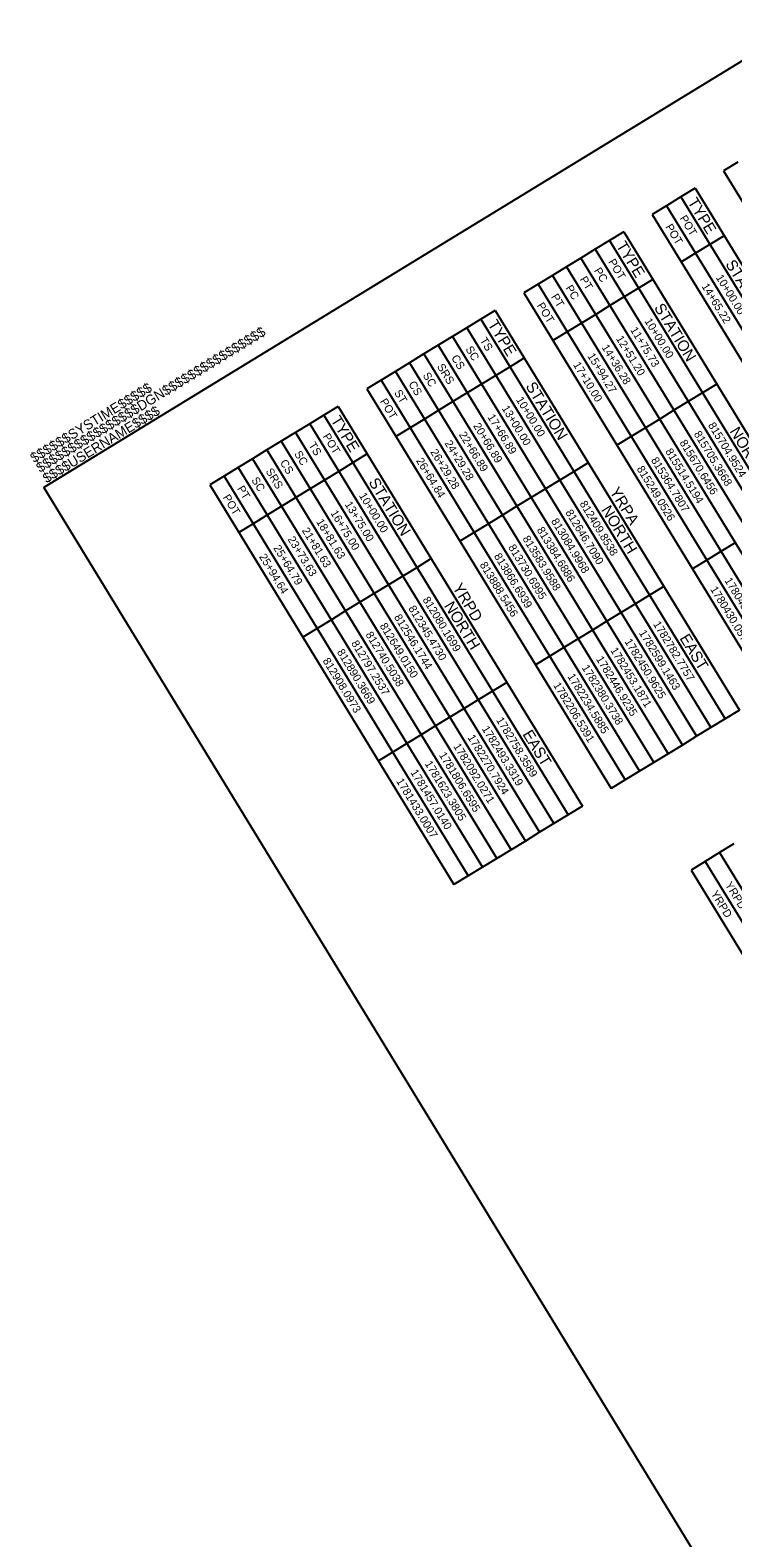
# Model space of a CAD drawing. Extents: x 1753086 to 1770987, y 792577 to 812636.
# Drawn here: x 1753086 to 1756968, y 800134 to 808460 of the extents above; entities that cross this region are included whole.
import ezdxf

# ---------------------------------------------------------------- set-up
doc = ezdxf.new("R2010")
doc.units = 0
for name, color, linetype in [('CTL Sheet Border CELL', 7, 'Continuous'), ('CTL Sheet Notes CELL', 7, 'Continuous'), ('CTL Sheet Table Cell', 7, 'Continuous'), ('CTL Sheet Text', 7, 'Continuous'), ('Sheet Data Field CELL', 7, 'Continuous')]:
    doc.layers.add(name, color=color, linetype=linetype)

msp = doc.modelspace()

# ---------------------------------------------------------------- linework, layer by layer
at = {"layer": 'CTL Sheet Border CELL'}
msp.add_lwpolyline([(1770671.7, 798289.4), (1762511, 811645.8), (1753161.6, 805933.4), (1761322.3, 792577)], close=True, dxfattribs=at)
at = {"layer": 'CTL Sheet Table Cell'}
for p, q in [((1756995.9, 807731.2), (1756917, 807683)), ((1756917, 807683), (1758266, 805475.3)), ((1756759.3, 807586.6), (1756680.5, 807538.5)), ((1756759.3, 807586.6), (1758108.3, 805378.9)), ((1756601.7, 807490.3), (1756522.8, 807442.1)), ((1756680.5, 807538.5), (1756601.7, 807490.3)), ((1756601.7, 807490.3), (1757950.6, 805282.6)), ((1756680.5, 807538.5), (1758029.4, 805330.7)), ((1756522.8, 807442.1), (1757871.7, 805234.4)), ((1756286.3, 807297.6), (1756207.4, 807249.4)), ((1756365.1, 807345.8), (1756286.3, 807297.6)), ((1756286.3, 807297.6), (1757635.2, 805089.9)), ((1756365.1, 807345.8), (1757714, 805138)), ((1756919.9, 807323.8), (1756841.1, 807275.6)), ((1756207.4, 807249.4), (1756128.6, 807201.2)), ((1756207.4, 807249.4), (1757556.3, 805041.7)), ((1756762.2, 807227.5), (1756683.4, 807179.3)), ((1756841.1, 807275.6), (1756762.2, 807227.5)), ((1756049.7, 807153), (1755970.9, 807104.9)), ((1756128.6, 807201.2), (1756049.7, 807153)), ((1756049.7, 807153), (1757398.6, 804945.3)), ((1756128.6, 807201.2), (1757477.5, 804993.5)), ((1755892, 807056.7), (1755813.2, 807008.5)), ((1755970.9, 807104.9), (1755892, 807056.7)), ((1755892, 807056.7), (1757240.9, 804849)), ((1755970.9, 807104.9), (1757319.8, 804897.2)), ((1756525.7, 807082.9), (1756446.8, 807034.8)), ((1755813.2, 807008.5), (1757162.1, 804800.8)), ((1756368, 806986.6), (1756289.2, 806938.4)), ((1756446.8, 807034.8), (1756368, 806986.6)), ((1755655.5, 806912.2), (1755576.6, 806864)), ((1755655.5, 806912.2), (1757004.4, 804704.5)), ((1756210.3, 806890.2), (1756131.5, 806842.1)), ((1756289.2, 806938.4), (1756210.3, 806890.2)), ((1755497.8, 806815.8), (1755418.9, 806767.6)), ((1755576.6, 806864), (1755497.8, 806815.8)), ((1755497.8, 806815.8), (1756846.7, 804608.1)), ((1755576.6, 806864), (1756925.6, 804656.3)), ((1756052.6, 806793.9), (1755973.8, 806745.7)), ((1756131.5, 806842.1), (1756052.6, 806793.9)), ((1755340.1, 806719.5), (1755261.2, 806671.3)), ((1755418.9, 806767.6), (1755340.1, 806719.5)), ((1755340.1, 806719.5), (1756689, 804511.7)), ((1755418.9, 806767.6), (1756767.9, 804559.9)), ((1755261.2, 806671.3), (1755182.4, 806623.1)), ((1755261.2, 806671.3), (1756610.2, 804463.6)), ((1755816.1, 806649.3), (1755737.2, 806601.2)), ((1755103.6, 806574.9), (1755024.7, 806526.8)), ((1755182.4, 806623.1), (1755103.6, 806574.9)), ((1755103.6, 806574.9), (1756452.5, 804367.2)), ((1755182.4, 806623.1), (1756531.3, 804415.4)), ((1755658.4, 806553), (1755579.5, 806504.8)), ((1755737.2, 806601.2), (1755658.4, 806553)), ((1755024.7, 806526.8), (1754945.9, 806478.6)), ((1754945.9, 806478.6), (1756294.8, 804270.9)), ((1755024.7, 806526.8), (1756373.6, 804319)), ((1755579.5, 806504.8), (1755500.7, 806456.6)), ((1756879, 806504.7), (1756800.1, 806456.5)), ((1754788.2, 806382.2), (1754709.3, 806334.1)), ((1754788.2, 806382.2), (1756137.1, 804174.5)), ((1755421.8, 806408.5), (1755343, 806360.3)), ((1755500.7, 806456.6), (1755421.8, 806408.5)), ((1756721.3, 806408.4), (1756642.4, 806360.2)), ((1756800.1, 806456.5), (1756721.3, 806408.4)), ((1754709.3, 806334.1), (1754630.5, 806285.9)), ((1754709.3, 806334.1), (1756058.2, 804126.3)), ((1755264.1, 806312.1), (1755185.3, 806263.9)), ((1755343, 806360.3), (1755264.1, 806312.1)), ((1756563.6, 806312), (1756484.7, 806263.8)), ((1756642.4, 806360.2), (1756563.6, 806312)), ((1754551.6, 806237.7), (1754472.8, 806189.5)), ((1754630.5, 806285.9), (1754551.6, 806237.7)), ((1754551.6, 806237.7), (1755900.5, 804030)), ((1754630.5, 806285.9), (1755979.4, 804078.2)), ((1755185.3, 806263.9), (1755106.4, 806215.8)), ((1756405.9, 806215.7), (1756327.1, 806167.5)), ((1756484.7, 806263.8), (1756405.9, 806215.7)), ((1754393.9, 806141.4), (1754315.1, 806093.2)), ((1754472.8, 806189.5), (1754393.9, 806141.4)), ((1754393.9, 806141.4), (1755742.8, 803933.6)), ((1754472.8, 806189.5), (1755821.7, 803981.8)), ((1754236.2, 806045), (1754157.4, 805996.8)), ((1754315.1, 806093.2), (1754236.2, 806045)), ((1754236.2, 806045), (1755585.2, 803837.3)), ((1754315.1, 806093.2), (1755664, 803885.5)), ((1754869.9, 806071.2), (1754791.1, 806023.1)), ((1754948.8, 806119.4), (1754869.9, 806071.2)), ((1756169.4, 806071.1), (1756090.5, 806023)), ((1754157.4, 805996.8), (1754078.5, 805948.7)), ((1754157.4, 805996.8), (1755506.3, 803789.1)), ((1754712.2, 805974.9), (1754633.4, 805926.7)), ((1754791.1, 806023.1), (1754712.2, 805974.9)), ((1756011.7, 805974.8), (1755932.8, 805926.6)), ((1756090.5, 806023), (1756011.7, 805974.8)), ((1754078.5, 805948.7), (1755427.5, 803740.9)), ((1754554.5, 805878.5), (1754475.7, 805830.4)), ((1754633.4, 805926.7), (1754554.5, 805878.5)), ((1755854, 805878.4), (1755775.1, 805830.3)), ((1755932.8, 805926.6), (1755854, 805878.4)), ((1754475.7, 805830.4), (1754396.8, 805782.2)), ((1755775.1, 805830.3), (1755696.3, 805782.1)), ((1754318, 805734), (1754239.1, 805685.8)), ((1754396.8, 805782.2), (1754318, 805734)), ((1755617.4, 805733.9), (1755538.6, 805685.7)), ((1755696.3, 805782.1), (1755617.4, 805733.9)), ((1755538.6, 805685.7), (1755459.7, 805637.6)), ((1756981.1, 805628.7), (1756902.3, 805580.5)), ((1756902.3, 805580.5), (1756823.4, 805532.3)), ((1755223.2, 805493), (1755144.3, 805444.9)), ((1755302, 805541.2), (1755223.2, 805493)), ((1756823.4, 805532.3), (1756744.6, 805484.1)), ((1755065.5, 805396.7), (1754986.7, 805348.5)), ((1755144.3, 805444.9), (1755065.5, 805396.7)), ((1756586.9, 805387.8), (1756508, 805339.6)), ((1754907.8, 805300.3), (1754829, 805252.1)), ((1754986.7, 805348.5), (1754907.8, 805300.3)), ((1756508, 805339.6), (1756429.2, 805291.4)), ((1754829, 805252.1), (1754750.1, 805204)), ((1756350.3, 805243.3), (1756271.5, 805195.1)), ((1756429.2, 805291.4), (1756350.3, 805243.3)), ((1754671.3, 805155.8), (1754592.4, 805107.6)), ((1754750.1, 805204), (1754671.3, 805155.8)), ((1756192.6, 805146.9), (1756113.8, 805098.7)), ((1756271.5, 805195.1), (1756192.6, 805146.9)), ((1756035, 805050.6), (1755956.1, 805002.4)), ((1756113.8, 805098.7), (1756035, 805050.6)), ((1755956.1, 805002.4), (1755877.3, 804954.2)), ((1755640.7, 804809.7), (1755561.9, 804761.5)), ((1755719.6, 804857.9), (1755640.7, 804809.7)), ((1755483, 804713.3), (1755404.2, 804665.2)), ((1755561.9, 804761.5), (1755483, 804713.3)), ((1755404.2, 804665.2), (1755325.3, 804617)), ((1756925.6, 804656.3), (1756846.7, 804608.1)), ((1757004.4, 804704.5), (1756925.6, 804656.3)), ((1755246.5, 804568.8), (1755167.6, 804520.6)), ((1755325.3, 804617), (1755246.5, 804568.8)), ((1756767.9, 804559.9), (1756689, 804511.7)), ((1756846.7, 804608.1), (1756767.9, 804559.9)), ((1755088.8, 804472.5), (1755009.9, 804424.3)), ((1755167.6, 804520.6), (1755088.8, 804472.5)), ((1756610.2, 804463.6), (1756531.3, 804415.4)), ((1756689, 804511.7), (1756610.2, 804463.6)), ((1756531.3, 804415.4), (1756452.5, 804367.2)), ((1756373.6, 804319), (1756294.8, 804270.9)), ((1756452.5, 804367.2), (1756373.6, 804319)), ((1756137.1, 804174.5), (1756058.2, 804126.3)), ((1755979.4, 804078.2), (1755900.5, 804030)), ((1756058.2, 804126.3), (1755979.4, 804078.2)), ((1755821.7, 803981.8), (1755742.8, 803933.6)), ((1755900.5, 804030), (1755821.7, 803981.8)), ((1756973.3, 803965.9), (1756894.5, 803917.7)), ((1755664, 803885.5), (1755585.2, 803837.3)), ((1755742.8, 803933.6), (1755664, 803885.5)), ((1756894.5, 803917.7), (1756815.6, 803869.5)), ((1756894.5, 803917.7), (1758693, 800974.1)), ((1755585.2, 803837.3), (1755506.3, 803789.1)), ((1756815.6, 803869.5), (1756736.8, 803821.4)), ((1756736.8, 803821.4), (1758535.3, 800877.7)), ((1756815.6, 803869.5), (1758614.2, 800925.9)), ((1755506.3, 803789.1), (1755427.5, 803740.9))]:
    msp.add_line(p, q, dxfattribs=at)

# ---------------------------------------------------------------- texts
at = {"layer": 'CTL Sheet Notes CELL'}
for s, p in [('TYPE', (1756715.5, 807510.7)), ('TYPE', (1756321.3, 807269.8)), ('STATION', (1756924.7, 807168.4)), ('STATION', (1756530.4, 806927.5)), ('TYPE', (1755611.7, 806836.2)), ('STATION', (1755820.8, 806493.9)), ('TYPE', (1754744.3, 806306.3)), ('NORTH', (1756947.7, 806244.6)), ('STATION', (1754953.5, 805964)), ('YRPA', (1756284.7, 805912)), ('NORTH', (1756238.1, 805811)), ('YRPD', (1755417.3, 805382)), ('NORTH', (1755370.7, 805281.1)), ('EAST', (1756671.5, 805101.6)), ('EAST', (1755804.2, 804571.7))]:
    msp.add_text(s, height=61.6, rotation=301.42495, dxfattribs=at).set_placement(p)
at = {"layer": 'CTL Sheet Text'}
for s, p in [('POT', (1756593.4, 807373)), ('POT', (1756672.2, 807421.2)), ('PC ', (1756199.2, 807132.1)), ('POT', (1756278, 807180.3)), ('PC ', (1756041.5, 807035.7)), ('PT ', (1756120.3, 807083.9)), ('14+65.22', (1756793.4, 807045.6)), ('10+00.00', (1756872.3, 807093.8)), ('PT ', (1755962.6, 806987.6)), ('POT', (1755883.8, 806939.4)), ('11+75.73', (1756399.2, 806804.7)), ('10+00.00', (1756478, 806852.9)), ('SC ', (1755489.5, 806698.5)), ('TS ', (1755568.4, 806746.7)), ('14+36.28', (1756241.5, 806708.4)), ('12+51.20', (1756320.4, 806756.5)), ('CS ', (1755410.7, 806650.3)), ('17+10.00', (1756083.8, 806612)), ('15+94.27', (1756162.7, 806660.2)), ('SC ', (1755253, 806554)), ('SRS', (1755331.8, 806602.2)), ('ST ', (1755095.3, 806457.6)), ('CS ', (1755174.2, 806505.8)), ('POT', (1755016.5, 806409.5)), ('13+00.00', (1755689.6, 806371.1)), ('10+00.00', (1755768.4, 806419.3)), ('17+66.89', (1755610.7, 806323)), ('815704.9524', (1756829.3, 806278)), ('POT', (1754701.1, 806216.8)), ('22+66.89', (1755453, 806226.6)), ('20+66.89', (1755531.9, 806274.8)), ('815705.3668', (1756750.5, 806229.8)), ('SC ', (1754543.4, 806120.4)), ('TS ', (1754622.2, 806168.6)), ('26+29.28', (1755295.3, 806130.2)), ('24+29.28', (1755374.2, 806178.4)), ('815514.5194', (1756592.8, 806133.5)), ('815670.6456', (1756671.6, 806181.6)), ('CS ', (1754464.5, 806072.2)), ('26+64.84', (1755216.5, 806082.1)), ('815249.0526', (1756435.1, 806037.1)), ('815364.7807', (1756513.9, 806085.3)), ('SC ', (1754306.8, 805975.9)), ('SRS', (1754385.7, 806024.1)), ('POT', (1754149.1, 805879.5)), ('PT ', (1754228, 805927.7)), ('10+00.00', (1754901.1, 805889.4)), ('16+75.00', (1754743.4, 805793)), ('13+75.00', (1754822.3, 805841.2)), ('812646.7090', (1756040.8, 805796.2)), ('812409.8538', (1756119.7, 805844.4)), ('21+81.63', (1754585.7, 805696.7)), ('18+81.63', (1754664.6, 805744.8)), ('813384.6886', (1755883.1, 805699.9)), ('813084.9968', (1755962, 805748)), ('23+73.63', (1754506.9, 805648.5)), ('813583.9588', (1755804.3, 805651.7)), ('25+94.64', (1754349.2, 805552.1)), ('25+64.79', (1754428, 805600.3)), ('813866.6939', (1755646.6, 805555.3)), ('813730.6995', (1755725.5, 805603.5)), ('813888.5456', (1755567.8, 805507.2)), ('1780430.0579', (1756841.2, 805372.4)), ('1780430.6642', (1756920.1, 805420.6)), ('812080.1699', (1755252.4, 805314.5)), ('812546.1744', (1755094.7, 805218.1)), ('812345.4730', (1755173.5, 805266.3)), ('812740.5038', (1754937, 805121.8)), ('812649.0150', (1755015.8, 805169.9)), ('1782599.1463', (1756447, 805131.5)), ('1782782.7757', (1756525.8, 805179.7)), ('812797.2537', (1754858.1, 805073.6)), ('1782453.1871', (1756289.3, 805035.2)), ('1782450.9625', (1756368.1, 805083.3)), ('812908.0973', (1754700.4, 804977.2)), ('812890.3669', (1754779.3, 805025.4)), ('1782446.9235', (1756210.4, 804987)), ('1782234.5885', (1756052.7, 804890.6)), ('1782380.3738', (1756131.6, 804938.8)), ('1782206.5391', (1755973.9, 804842.5)), ('1782758.3589', (1755658.5, 804649.8)), ('1782270.7924', (1755500.8, 804553.4)), ('1782493.3319', (1755579.7, 804601.6)), ('1781806.6595', (1755343.1, 804457)), ('1782092.0271', (1755422, 804505.2)), ('1781623.3805', (1755264.3, 804408.9)), ('1781433.0007', (1755106.6, 804312.5)), ('1781457.0140', (1755185.4, 804360.7)), ('YRPD', (1756844.2, 803692)), ('YRPD', (1756923, 803740.2))]:
    msp.add_text(s, height=44, rotation=301.42495, dxfattribs=at).set_placement(p)
at = {"layer": 'Sheet Data Field CELL'}
for s, p in [('$$$$$$$$$$$$$$$$DGN$$$$$$$$$$$$$$$$', (1753141, 806014.1)), ('$$$$$$SYSTIME$$$$$', (1753108.1, 806068)), ('$$$$USERNAME$$$$', (1753176.9, 805955.7))]:
    msp.add_text(s, height=54.783, rotation=31.42495, dxfattribs=at).set_placement(p)

doc.saveas('drawing.dxf')
